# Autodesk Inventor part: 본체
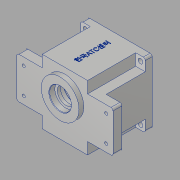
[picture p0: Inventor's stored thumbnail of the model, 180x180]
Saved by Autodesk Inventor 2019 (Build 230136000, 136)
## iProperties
Created: 2020-01
Part Number: 본체
Material: 알루미늄 6061
Document SubType Name: Modeling
Designer: 323-3
Density: 2.7 g/cm^3
Appearance: 알루미늄 - 평지
Mass: 876.486 g
Surface Area: 793.573 cm^2
Volume: 324.624 cm^3
Author: 323-3
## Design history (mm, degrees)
sketch "스케치4"
  geometry: L1 (47, -47)-(-47, -47); L2 (-47, -47)-(-47, 47); L3 (-47, 47)-(47, 47); L4 (47, 47)-(47, -47); L5 (47, -47)-(-47, 47); L6 (-47, -47)-(47, 47); 1 further point
  constraints: 12 end point, 2 midpoint, 2 parallel, 1 horizontal, 1 perpendicular
  dimensions: "d11" = 94 distance of L2.end L3.end; "d12" = 94 distance of L1.end L2.end
extrude "돌출4" new body sketch "스케치4" distance "d13" = 80; taper "d14" = 0 deg
sketch "스케치5"
  geometry: L1 (70, -30)-(-70, -30); L2 (-70, -30)-(-70, 30); L3 (-70, 30)-(70, 30); L4 (70, 30)-(70, -30); L5 (70, -30)-(-70, 30); L6 (-70, -30)-(70, 30); 1 further point
  constraints: 12 end point, 2 midpoint, 2 parallel, 1 horizontal, 1 perpendicular
  dimensions: "d15" = 140 distance of L2.end L3.end; "d16" = 60 distance of L1.end L2.end
extrude "돌출5" join sketch "스케치5" distance "d17" = 13; taper "d18" = 0 deg
sketch "스케치6"
  geometry: C1 r 40 at (0, 0); 1 further point
  constraints: 1 centre point, 1 coincident
  dimensions: "d19" = 80 diameter of C1
extrude "돌출6" cut sketch "스케치6" distance "d20" = 71; taper "d21" = 0 deg
sketch "스케치7"
  geometry: C1 r 21 at (0, 11); C2 r 15 at (0, -20); 1 further point
  constraints: 2 centre point, 2 vertical alignment
  dimensions: "d22" = 42 diameter of C1; "d23" = 11 distance of point (0, 0) C1.centre; "d24" = 30 diameter of C2; "d25" = 20 distance of C2.centre point (0, 0)
extrude "돌출7" join sketch "스케치7" distance "d26" = 7; taper "d27" = 0 deg
fillet "모깎기1" dims "d28" = 3
sketch "스케치8"
  geometry: C1 r 17.5 at (0, 11); A1 r 21 centre (0, 11) between (12.163, -6.119) and (-12.163, -6.119) reference; A2 r 3 centre (-13.901, -8.565) between (-11.584, -10.47) and (-12.163, -6.119) reference; A3 r 15 centre (0, -20) between (-11.584, -10.47) and (11.584, -10.47) reference; A4 r 3 centre (13.901, -8.565) between (12.163, -6.119) and (11.584, -10.47) reference; 1 further point
  constraints: 1 centre point, 1 coincident
  dimensions: "d29" = 35 diameter of C1
extrude "돌출8" cut sketch "스케치8" distance "d30" = 10; taper "d31" = 0 deg
sketch "스케치9"
  geometry: C1 r 17.5 at (0, 11) reference; C2 r 11 at (0, -20); A1 r 21 centre (0, 11) between (12.163, -6.119) and (-12.163, -6.119) reference; A2 r 3 centre (-13.901, -8.565) between (-11.584, -10.47) and (-12.163, -6.119) reference; A3 r 15 centre (0, -20) between (-11.584, -10.47) and (11.584, -10.47) reference; A4 r 3 centre (13.901, -8.565) between (12.163, -6.119) and (11.584, -10.47) reference; 1 further point
  constraints: 1 centre point, 1 coincident
  dimensions: "d32" = 22 diameter of C2
extrude "돌출9" cut sketch "스케치9" distance "d33" = 7; taper "d34" = 0 deg
sketch "스케치10"
  geometry: C1 r 11 at (0, 0) reference; C2 r 9.5 at (0, 0); 1 further point
  constraints: 1 centre point, 1 coincident
  dimensions: "d35" = 19 diameter of C2
extrude "돌출10" cut sketch "스케치10" distance "d36" = 3; taper "d37" = 0 deg
chamfer "모따기1" distance "d38" = 1; stored, may be unused: second distance "d39" = 2, angle "d40" = 45 deg
sketch "스케치11"
  geometry: C1 r 27.5 at (0, 11); 1 further point
  constraints: 1 centre point, 1 vertical alignment
  dimensions: "d41" = 55 diameter of C1; "d42" = 11 distance of point (0, 0) C1.centre
extrude "돌출11" join sketch "스케치11" distance "d43" = 7; taper "d44" = 0 deg
sketch "스케치12"
  geometry: C1 r 27.5 at (0, 0) reference; C2 r 16 at (0, 0); 1 further point
  constraints: 1 centre point, 1 coincident
  dimensions: "d45" = 32 diameter of C2
extrude "돌출12" cut sketch "스케치12" distance "d46" = 8.3; taper "d47" = 0 deg
sketch "스케치13"
  geometry: C1 r 16 at (0, 0) reference; C2 r 12.5 at (0, 0); 1 further point
  constraints: 1 centre point, 1 coincident
  dimensions: "d48" = 25 diameter of C2
extrude "돌출13" cut sketch "스케치13" distance "d49" = 9.2; taper "d50" = 0 deg
chamfer "모따기2" distance "d51" = 0.8; stored, may be unused: second distance "d52" = 2, angle "d53" = 30 deg
fillet "모깎기2" dims "d54" = 3
sketch "스케치14"
  geometry: C1 r 43 at (0, 0); 1 further point
  constraints: 1 centre point, 1 coincident
  dimensions: "d55" = 86 diameter of C1
extrude "돌출14" cut sketch "스케치14" distance "d56" = 9; taper "d57" = 0 deg
chamfer "모따기3" distance "d58" = 1; stored, may be unused: second distance "d59" = 2, angle "d60" = 30 deg
sketch "스케치15" dims "d61" = 72
  geometry: L1 (36, 4)-(39.799, 4); L2 (36, -4)-(39.799, -4); A1 r 4 centre (36, 0) between (36, 4) and (36, -4); A2 r 40 centre (0, 0) between (39.799, 4) and (39.799, -4) reference; A3 r 4 centre (36, 0) between (40, 0) and (36, 4); A4 r 4 centre (36, 0) between (36, -4) and (40, 0); 2 further points
  constraints: 9 point on circle, 4 end point, 4 tangent, 3 centre point, 2 horizontal, 2 horizontal alignment, 1 coincident, 2 other
  dimensions: "d62" = 8 diameter of A1
extrude "돌출15" join sketch "스케치15" stored distance "d63" = 9; taper "d64" = 0 deg
fillet "모깎기3" dims "d65" = 3
sketch "스케치16"
  geometry: A1 r 4 centre (36, 0) between (36, 4) and (36, -4) reference; 2 further points
  constraints: 1 coincident
hole "구멍1" sketch "스케치16" at (36, 0) diameter "d66" = 3.242; stored, may be unused: countersink angle "d70" = 90 deg, drill point angle "d72" = 118 deg; dims "d67" = 7, "d68" = 4, "d69" = 2, "d71" = 9
sketch "스케치18"
  geometry: C1 r 5 at (-60, 19); 1 further point
  constraints: 1 centre point
  dimensions: "d74" = 10 diameter of C1; "d75" = 60 horizontal distance of C1.centre point (0, 0); "d76" = 19 vertical distance of C1.centre point (0, 0)
hole "구멍2" sketch "스케치18" at (-60, 19) diameter "d77" = 4.5; stored, may be unused: countersink angle "d81" = 90 deg, drill point angle "d83" = 118 deg; dims "d78" = 7, "d79" = 10, "d80" = 5, "d82" = 9
sketch "스케치19"
  geometry: L1 (47, 47)-(47, 30) reference; L2 (47, 47)-(33, 47); L3 (33, 47)-(33, 30); L4 (33, 30)-(47, 30); L5 (47, 30)-(47, 47); 1 further point
  constraints: 8 end point, 2 parallel, 1 horizontal, 1 perpendicular
  dimensions: "d84" = 33 distance from line of L3 point (0, 0); "d85" = 30 distance from line of point (0, 0) L4
extrude "돌출16" cut sketch "스케치19" distance "d86" = 70; taper "d87" = 0 deg
sketch "스케치20"
  geometry: C1 r 3.5 at (40, 40); 1 further point
  constraints: 1 centre point
  dimensions: "d88" = 7 diameter of C1; "d89" = 40 horizontal distance of C1.centre point (0, 0); "d90" = 40 horizontal distance of C1.centre point (0, 0)
extrude "돌출17" cut sketch "스케치20" distance "d91" = 70; taper "d92" = 0 deg
fillet "모깎기4" dims "d93" = 3
fillet "모깎기5" dims "d94" = 3
sketch "스케치21"
  geometry: L1 (-77, 80)-(11, 80) reference; L2 (-66, 0)-(0, 0) reference; 3 further points
  constraints: 1 midpoint, 1 vertical alignment, 1 other
  dimensions: "d97" = 40 distance from line of L1 point (-33, 40)
feature "엠보싱1" sketch "스케치21" dims "d95" = 0.5, "d96" = 0
node "솔리드2"
mirror "미러1"
mirror "미러2"
mirror "미러3"
mirror "미러4"
mirror "미러5"
mirror "미러6"
mirror "미러7"
mirror "미러8"
node "투영된 루프1"
node "투영된 루프2"
node "투영된 루프3"
node "투영된 루프4"
node "투영된 루프5"
